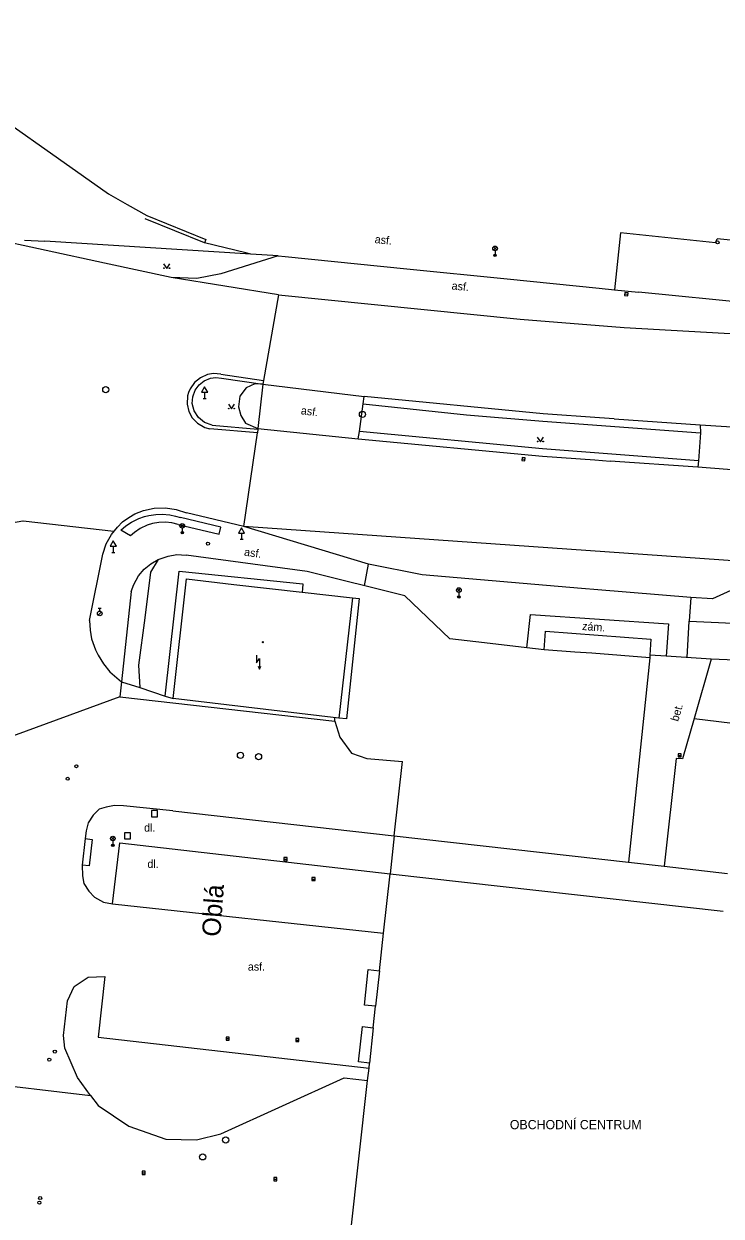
# Model space of a CAD drawing. Extents: x -602419 to -601554, y -1162937 to -1162362.
# Drawn here: x -601963.7 to -601907, y -1162488.6 to -1162391.7 of the extents above; entities that cross this region are included whole.
import ezdxf

# ---------------------------------------------------------------- set-up
doc = ezdxf.new("R2010")
doc.units = 0
doc.layers.add('Podklad', color=7, linetype='Continuous')

msp = doc.modelspace()

# ---------------------------------------------------------------- linework, layer by layer
at = {"layer": 'Podklad'}
for p, q in [((-601925.5225, -1162410.11), (-601925.2575, -1162409.845)), ((-601925.5225, -1162409.845), (-601925.2575, -1162410.11)), ((-601925.39, -1162410.165), (-601925.39, -1162410.54)), ((-601914.8544, -1162413.6782), (-601914.6056, -1162413.7018)), ((-601949.105, -1162422.1599), (-601948.855, -1162422.1599)), ((-601948.98, -1162421.6509), (-601948.98, -1162422.1599)), ((-601923.2142, -1162427.0756), (-601922.9658, -1162427.1044)), ((-601950.9325, -1162432.64), (-601950.6675, -1162432.375)), ((-601950.9325, -1162432.375), (-601950.6675, -1162432.64)), ((-601950.8, -1162432.695), (-601950.8, -1162433.07)), ((-601946.105, -1162433.6), (-601945.855, -1162433.6)), ((-601945.98, -1162433.091), (-601945.98, -1162433.6)), ((-601956.525, -1162434.68), (-601956.275, -1162434.68)), ((-601956.4, -1162434.171), (-601956.4, -1162434.68)), ((-601928.4625, -1162437.86), (-601928.1975, -1162437.595)), ((-601928.4625, -1162437.595), (-601928.1975, -1162437.86)), ((-601928.33, -1162437.915), (-601928.33, -1162438.29)), ((-601957.629, -1162439.756), (-601957.364, -1162439.491)), ((-601957.625, -1162439.1825), (-601957.375, -1162439.1825)), ((-601957.5, -1162439.4325), (-601957.5, -1162439.1825)), ((-601910.515, -1162451.15), (-601910.265, -1162451.15)), ((-601956.5725, -1162458.03), (-601956.3075, -1162457.765)), ((-601956.5725, -1162457.765), (-601956.3075, -1162458.03)), ((-601956.44, -1162458.085), (-601956.44, -1162458.46)), ((-601942.5349, -1162459.58), (-601942.2849, -1162459.58)), ((-601940.265, -1162461.2), (-601940.015, -1162461.2)), ((-601947.245, -1162474.15), (-601946.995, -1162474.15)), ((-601941.575, -1162474.27), (-601941.325, -1162474.27)), ((-601954.065, -1162485.05), (-601953.815, -1162485.05)), ((-601943.365, -1162485.57), (-601943.115, -1162485.57))]:
    msp.add_line(p, q, dxfattribs=at)
for points in [[(-601977.2199, -1162391.74), (-601975.27, -1162392.7), (-601971.17, -1162395.45), (-601969.4699, -1162396.62), (-601956.79, -1162405.54), (-601955.27, -1162406.4), (-601953.68, -1162407.3), (-601948.87, -1162409.25), (-601948.98, -1162409.52)], [(-601948.98, -1162409.52), (-601953.82, -1162407.57)], [(-601943, -1162410.58), (-601947.67, -1162412.04), (-601949.61, -1162412.43), (-601951.69, -1162412.34), (-601957.12, -1162411.17), (-601966.61, -1162409.13)], [(-601963.61, -1162409.31), (-601961.96, -1162409.4)], [(-601943, -1162410.58), (-601945.24, -1162410.44), (-601961.96, -1162409.4)], [(-601945.24, -1162410.44), (-601945.6297, -1162410.3452), (-601948.98, -1162409.52)], [(-601915.19, -1162408.71), (-601915.69, -1162413.329)], [(-601907.49, -1162409.52), (-601915.19, -1162408.71)], [(-601907.49, -1162409.52), (-601907.36, -1162409.19)], [(-601905.73, -1162409.35), (-601907.36, -1162409.19)], [(-601943, -1162410.58), (-601942.44, -1162410.63)], [(-601942.44, -1162410.63), (-601932.57, -1162411.63)], [(-601952.31, -1162411.235), (-601952.06, -1162411.61), (-601951.81, -1162411.235)], [(-601942.974, -1162413.752), (-601951.69, -1162412.34)], [(-601932.57, -1162411.63), (-601924.4099, -1162412.45)], [(-601924.4099, -1162412.45), (-601916.94, -1162413.2)], [(-601916.94, -1162413.2), (-601915.69, -1162413.33), (-601913.74, -1162413.53)], [(-601904.46, -1162414.45), (-601913.74, -1162413.53)], [(-601942.974, -1162413.752), (-601944.21, -1162420.7)], [(-601942.974, -1162413.752), (-601923.36, -1162415.7179), (-601914.899, -1162416.4019), (-601902.977, -1162417.0849), (-601901.6822, -1162417.0998), (-601901.1795, -1162417.1051), (-601901.1621, -1162417.1057), (-601897.689, -1162417.1448)], [(-601947.6599, -1162420.2), (-601948.27, -1162420.15), (-601948.76, -1162420.21), (-601949.32, -1162420.48), (-601949.81, -1162420.87), (-601950.15, -1162421.39), (-601950.29, -1162421.69), (-601950.36, -1162421.95), (-601950.4099, -1162422.64), (-601950.27, -1162423.2199), (-601949.98, -1162423.74), (-601949.55, -1162424.1599), (-601948.9699, -1162424.52), (-601948.56, -1162424.62)], [(-601947.6599, -1162420.2), (-601944.21, -1162420.7), (-601944.25, -1162420.99)], [(-601948.38, -1162424.33), (-601948.98, -1162424.11), (-601949.48, -1162423.7199), (-601949.83, -1162423.18), (-601949.98, -1162422.56), (-601949.94, -1162422.02), (-601949.76, -1162421.5), (-601949.43, -1162421.07), (-601949.02, -1162420.7199), (-601948.51, -1162420.51), (-601948.07, -1162420.46), (-601947.6, -1162420.51)], [(-601947.6, -1162420.51), (-601944.25, -1162420.99)], [(-601944.25, -1162420.99), (-601944.893, -1162420.9659), (-601945.606, -1162421.3069), (-601946.134, -1162421.988), (-601946.233, -1162422.8559), (-601946.046, -1162423.5369), (-601945.672, -1162424.1629), (-601944.65, -1162424.59)], [(-601944.25, -1162420.99), (-601944.65, -1162424.59)], [(-601944.25, -1162420.99), (-601936.01, -1162422.01)], [(-601936.1, -1162422.6), (-601936.01, -1162422.01)], [(-601916.92, -1162423.73), (-601921.49, -1162423.4), (-601936.01, -1162422.01)], [(-601947.05, -1162422.635), (-601946.8, -1162423.01), (-601946.55, -1162422.635)], [(-601936.1, -1162422.6), (-601927.7, -1162423.49), (-601921.5, -1162424), (-601908.71, -1162424.95), (-601908.87, -1162427.24), (-601921.54, -1162426.25), (-601936.4099, -1162424.86)], [(-601936.4099, -1162424.86), (-601936.1, -1162422.6)], [(-601915.7199, -1162423.81), (-601916.92, -1162423.73)], [(-601915.7199, -1162423.81), (-601908.74, -1162424.31), (-601906.58, -1162424.44), (-601903.8, -1162424.49), (-601902.51, -1162424.51)], [(-601944.6599, -1162424.65), (-601944.69, -1162424.95), (-601948.56, -1162424.62)], [(-601948.38, -1162424.33), (-601944.6599, -1162424.65)], [(-601901.6, -1162435.65), (-601903.1262, -1162435.5438), (-601903.2493, -1162435.535), (-601903.7384, -1162435.5009), (-601945.81, -1162432.57), (-601944.69, -1162424.95)], [(-601944.65, -1162424.59), (-601944.6599, -1162424.65)], [(-601944.65, -1162424.59), (-601936.5, -1162425.45)], [(-601936.5, -1162425.45), (-601936.4099, -1162424.86)], [(-601908.74, -1162424.31), (-601908.71, -1162424.95)], [(-601936.5, -1162425.45), (-601921.55, -1162426.86), (-601917.28, -1162427.1599)], [(-601921.96, -1162425.305), (-601921.71, -1162425.68), (-601921.46, -1162425.305)], [(-601917.28, -1162427.1599), (-601916.05, -1162427.25)], [(-601902.9099, -1162428.07), (-601904.04, -1162428.07), (-601906.5, -1162427.92), (-601908.93, -1162427.75), (-601916.05, -1162427.25)], [(-601908.87, -1162427.24), (-601908.93, -1162427.7495)], [(-601957.24, -1162434.82), (-601956.9699, -1162433.98), (-601956.55, -1162433.2), (-601956.07, -1162432.62), (-601955.64, -1162432.18), (-601955.13, -1162431.82), (-601954.64, -1162431.54), (-601953.94, -1162431.25), (-601953.07, -1162431.06), (-601952.17, -1162431.05), (-601951.28, -1162431.17), (-601950.45, -1162431.46)], [(-601955.8, -1162432.86), (-601955.37, -1162432.5), (-601954.9099, -1162432.2), (-601954.33, -1162431.9099), (-601953.86, -1162431.75), (-601953.52, -1162431.67), (-601952.94, -1162431.58), (-601952.42, -1162431.56), (-601951.82, -1162431.61), (-601951.35, -1162431.71), (-601950.95, -1162431.83)], [(-601951.14, -1162432.39), (-601947.8, -1162433.18), (-601947.6599, -1162432.61), (-601950.95, -1162431.83)], [(-601945.81, -1162432.57), (-601950.45, -1162431.46)], [(-601956.3597, -1162432.9701), (-601963.7232, -1162432.1419), (-601963.74, -1162432.1399), (-601965.62, -1162432.45)], [(-601955.01, -1162433.32), (-601955.8, -1162432.86)], [(-601951.14, -1162432.39), (-601951.65, -1162432.26), (-601952.17, -1162432.21), (-601952.69, -1162432.24), (-601953.21, -1162432.33), (-601953.65, -1162432.46), (-601954.2199, -1162432.73), (-601954.69, -1162433.04), (-601955.01, -1162433.32)], [(-601931.3, -1162436.5), (-601935.67, -1162435.63), (-601945.81, -1162432.57)], [(-601958.33, -1162440.2), (-601957.24, -1162434.82)], [(-601954.94, -1162437.83), (-601954.74, -1162437.27), (-601954.34, -1162436.57), (-601953.88, -1162436.03), (-601953.34, -1162435.59), (-601952.75, -1162435.23), (-601951.94, -1162434.96), (-601951.23, -1162434.84), (-601950.4699, -1162434.88)], [(-601952.75, -1162435.23), (-601953.37, -1162436.28), (-601953.83, -1162439.99), (-601954.36, -1162443.82), (-601954.25, -1162445.65)], [(-601922.82, -1162442.4099), (-601926.26, -1162442), (-601929.06, -1162441.69), (-601932.7199, -1162438.2), (-601940.64, -1162436.21), (-601950.4699, -1162434.88)], [(-601935.999, -1162437.3761), (-601935.67, -1162435.63)], [(-601952.18, -1162446.33), (-601951.04, -1162436.18), (-601941, -1162437.21), (-601941.04, -1162437.62), (-601941.07, -1162437.89)], [(-601918.37, -1162437.59), (-601931.3, -1162436.5)], [(-601903.87, -1162436.68), (-601907.73, -1162438.44)], [(-601951.54, -1162446.54), (-601950.46, -1162436.82)], [(-601950.46, -1162436.82), (-601946.61, -1162437.26)], [(-601946.61, -1162437.26), (-601941.07, -1162437.89)], [(-601917.05, -1162437.7), (-601918.37, -1162437.59)], [(-601909.5, -1162438.34), (-601917.05, -1162437.7)], [(-601954.94, -1162437.83), (-601955.7199, -1162445.17)], [(-601941.07, -1162437.89), (-601936.9699, -1162438.35)], [(-601936.9699, -1162438.35), (-601938.07, -1162448.12)], [(-601936.9699, -1162438.35), (-601936.42, -1162438.4099), (-601937.4699, -1162448.19), (-601938.07, -1162448.12)], [(-601909.5, -1162438.34), (-601909.62, -1162440.26)], [(-601907.73, -1162438.44), (-601909.5, -1162438.34)], [(-601958.33, -1162440.2), (-601958.29, -1162440.9699), (-601958.1599, -1162441.69), (-601957.84, -1162442.59), (-601957.63, -1162443), (-601957.2, -1162443.7199), (-601956.68, -1162444.37), (-601955.7199, -1162445.17)], [(-601922.82, -1162442.4099), (-601922.5, -1162439.71)], [(-601922.5, -1162439.71), (-601911.3, -1162440.4699)], [(-601911.3, -1162440.4699), (-601911.5, -1162443.1)], [(-601909.7886, -1162443.2075), (-601909.62, -1162440.26)], [(-601909.62, -1162440.26), (-601904.3, -1162440.49)], [(-601921.39, -1162442.58), (-601921.3, -1162441.06)], [(-601921.3, -1162441.06), (-601912.73, -1162441.7)], [(-601921.39, -1162442.58), (-601922.82, -1162442.4099)], [(-601918.9099, -1162442.77), (-601921.39, -1162442.58)], [(-601912.73, -1162441.7), (-601912.81, -1162443.01)], [(-601944.78, -1162443.02), (-601944.78, -1162443.645), (-601944.53, -1162443.27), (-601944.53, -1162444.145)], [(-601917.54, -1162442.86), (-601918.9099, -1162442.77)], [(-601912.82, -1162443.2199), (-601917.54, -1162442.86)], [(-601912.82, -1162443.2199), (-601914.55, -1162459.83)], [(-601912.81, -1162443.01), (-601912.82, -1162443.2199)], [(-601911.5, -1162443.1), (-601912.81, -1162443.01)], [(-601907.84, -1162443.33), (-601911.5, -1162443.1)], [(-601907.84, -1162443.33), (-601909.23, -1162448.1599)], [(-601904.63, -1162443.48), (-601907.84, -1162443.33)], [(-601944.6395, -1162443.9005), (-601944.53, -1162444.145), (-601944.4205, -1162443.9005)], [(-601955.7199, -1162445.17), (-601955.86, -1162446.4), (-601938.4, -1162448.38)], [(-601955.72, -1162445.17), (-601954.25, -1162445.65), (-601952.18, -1162446.33)], [(-601955.86, -1162446.4), (-601965.11, -1162449.78)], [(-601952.18, -1162446.33), (-601951.54, -1162446.54)], [(-601938.07, -1162448.12), (-601951.54, -1162446.54)], [(-601938.4, -1162448.38), (-601938.4081, -1162448.0803)], [(-601938.4, -1162448.38), (-601937.99, -1162449.68), (-601937.04, -1162450.9699), (-601935.81, -1162451.39), (-601932.92, -1162451.6599)], [(-601909.23, -1162448.1599), (-601910.17, -1162451.44)], [(-601909.23, -1162448.1599), (-601905.2, -1162448.65)], [(-601933.58, -1162457.68), (-601932.92, -1162451.6599)], [(-601910.68, -1162451.4099), (-601911.65, -1162460.15)], [(-601910.17, -1162451.44), (-601910.68, -1162451.4099)], [(-601951.57, -1162455.6599), (-601955.58, -1162455.24), (-601956.3, -1162455.2199), (-601956.99, -1162455.35), (-601957.55, -1162455.53), (-601958.03, -1162456.01), (-601958.45, -1162456.64), (-601958.59, -1162457.29), (-601958.68, -1162457.9099)], [(-601951.57, -1162455.6599), (-601933.58, -1162457.68)], [(-601958.68, -1162457.9099), (-601958.93, -1162460.06)], [(-601958.68, -1162457.9099), (-601958.11, -1162457.98), (-601958.37, -1162460.12), (-601958.93, -1162460.06)], [(-601933.58, -1162457.68), (-601933.92, -1162460.76)], [(-601933.58, -1162457.68), (-601914.55, -1162459.83)], [(-601956.46, -1162463.21), (-601955.88, -1162458.25), (-601933.92, -1162460.76)], [(-601914.55, -1162459.83), (-601911.65, -1162460.15)], [(-601958.93, -1162460.06), (-601958.9, -1162460.93), (-601958.79, -1162461.56), (-601958.38, -1162462.18), (-601957.93, -1162462.67), (-601957.2, -1162463.08), (-601956.46, -1162463.21)], [(-601934.44, -1162465.6), (-601933.92, -1162460.76)], [(-601933.92, -1162460.76), (-601906.86, -1162463.81)], [(-601911.65, -1162460.15), (-601906.52, -1162460.73)], [(-601956.46, -1162463.21), (-601934.44, -1162465.6)], [(-601934.77, -1162468.64), (-601934.44, -1162465.6)], [(-601935.99, -1162471.43), (-601935.69, -1162468.54)], [(-601935.69, -1162468.54), (-601934.77, -1162468.64)], [(-601934.77, -1162468.64), (-601935.09, -1162471.53)], [(-601958.25, -1162478.76), (-601959.32, -1162477.32), (-601960.33, -1162474.92), (-601960.44, -1162473.89), (-601960.11, -1162471.08), (-601959.58, -1162469.92), (-601958.44, -1162469.1599), (-601957.08, -1162469.1), (-601957.62, -1162474.04), (-601935.63, -1162476.54)], [(-601935.09, -1162471.53), (-601935.99, -1162471.43)], [(-601935.28, -1162473.28), (-601935.09, -1162471.53)], [(-601936.4699, -1162476.05), (-601936.1599, -1162473.18)], [(-601936.1599, -1162473.18), (-601935.28, -1162473.28)], [(-601935.28, -1162473.28), (-601935.59, -1162476.15)], [(-601935.59, -1162476.15), (-601936.4699, -1162476.05)], [(-601935.63, -1162476.54), (-601935.59, -1162476.15)], [(-601958.25, -1162478.76), (-601957.64, -1162479.59), (-601955.14, -1162481.27), (-601952.14, -1162482.32), (-601949.64, -1162482.36), (-601947.6599, -1162481.88), (-601937.6599, -1162477.34), (-601935.74, -1162477.55)], [(-601935.74, -1162477.55), (-601935.63, -1162476.54)], [(-601967.9, -1162477.63), (-601958.25, -1162478.76)], [(-601937.12, -1162490.04), (-601935.74, -1162477.55)]]:
    msp.add_lwpolyline(points, dxfattribs=at)
for points in [[(-601914.8662, -1162413.8027), (-601914.6173, -1162413.8262), (-601914.5938, -1162413.5773), (-601914.8427, -1162413.5538)], [(-601949.23, -1162421.6509), (-601948.73, -1162421.6509), (-601948.98, -1162421.2179)], [(-601923.2285, -1162427.1998), (-601922.9802, -1162427.2285), (-601922.9515, -1162426.9802), (-601923.1998, -1162426.9515)], [(-601946.23, -1162433.091), (-601945.73, -1162433.091), (-601945.98, -1162432.658)], [(-601956.65, -1162434.171), (-601956.15, -1162434.171), (-601956.4, -1162433.738)], [(-601910.515, -1162451.275), (-601910.265, -1162451.275), (-601910.265, -1162451.025), (-601910.515, -1162451.025)], [(-601953.3, -1162456.14), (-601952.8, -1162456.14), (-601952.8, -1162455.64), (-601953.3, -1162455.64)], [(-601955.49, -1162457.94), (-601954.99, -1162457.94), (-601954.99, -1162457.44), (-601955.49, -1162457.44)], [(-601942.5349, -1162459.705), (-601942.2849, -1162459.705), (-601942.2849, -1162459.455), (-601942.5349, -1162459.455)], [(-601940.265, -1162461.325), (-601940.015, -1162461.325), (-601940.015, -1162461.075), (-601940.265, -1162461.075)], [(-601947.245, -1162474.275), (-601946.995, -1162474.275), (-601946.995, -1162474.025), (-601947.245, -1162474.025)], [(-601941.575, -1162474.395), (-601941.325, -1162474.395), (-601941.325, -1162474.145), (-601941.575, -1162474.145)], [(-601954.065, -1162485.175), (-601953.815, -1162485.175), (-601953.815, -1162484.925), (-601954.065, -1162484.925)], [(-601943.365, -1162485.695), (-601943.115, -1162485.695), (-601943.115, -1162485.445), (-601943.365, -1162485.445)]]:
    msp.add_lwpolyline(points, close=True, dxfattribs=at)
for centre, radius in [((-601907.32, -1162409.49), 0.125), ((-601925.39, -1162409.9775), 0.1875), ((-601925.39, -1162410.54), 0.1), ((-601925.39, -1162410.54), 0.0723), ((-601925.39, -1162410.54), 0.0438), ((-601952.2851, -1162411.5849), 0.025), ((-601951.8354, -1162411.5849), 0.025), ((-601957.01, -1162421.45), 0.25), ((-601947.0251, -1162422.9849), 0.025), ((-601946.5754, -1162422.9849), 0.025), ((-601936.1599, -1162423.46), 0.25), ((-601921.9351, -1162425.6549), 0.025), ((-601921.4854, -1162425.6549), 0.025), ((-601950.8, -1162432.5075), 0.1875), ((-601950.8, -1162433.07), 0.1), ((-601950.8, -1162433.07), 0.0723), ((-601950.8, -1162433.07), 0.0438), ((-601948.71, -1162433.95), 0.125), ((-601928.33, -1162437.7275), 0.1875), ((-601928.33, -1162438.29), 0.1), ((-601928.33, -1162438.29), 0.0723), ((-601928.33, -1162438.29), 0.0438), ((-601957.5, -1162439.62), 0.1875), ((-601944.26, -1162441.96), 0.045), ((-601944.26, -1162441.96), 0.0199), ((-601946.07, -1162451.15), 0.25), ((-601944.6, -1162451.26), 0.25), ((-601959.4, -1162452.03), 0.125), ((-601960.1, -1162453.05), 0.125), ((-601956.44, -1162457.8975), 0.1875), ((-601956.44, -1162458.46), 0.1), ((-601956.44, -1162458.46), 0.0723), ((-601956.44, -1162458.46), 0.0438), ((-601961.15, -1162475.21), 0.125), ((-601961.6, -1162475.86), 0.125), ((-601947.27, -1162482.39), 0.25), ((-601949.14, -1162483.76), 0.25), ((-601962.34, -1162487.1), 0.125), ((-601962.4, -1162487.48), 0.125)]:
    msp.add_circle(centre, radius, dxfattribs=at)

# ---------------------------------------------------------------- texts
for s, height, rotation, p in [('asf.', 0.65, 354.13, (-601935.19, -1162409.54)), ('asf.', 0.65, 354.377589, (-601928.94, -1162413.31)), ('asf.', 0.65, 352.94, (-601941.19, -1162423.44)), ('asf.', 0.65, 352.29, (-601945.8, -1162434.93)), (' zám.', 0.65, 356.12, (-601918.58, -1162440.95)), ('bet.', 0.65, 73.97, (-601910.52, -1162448.44)), ('Oblá', 1.5, 85.95, (-601947.71, -1162465.9099))]:
    msp.add_text(s, height=height, rotation=rotation, dxfattribs=at).set_placement(p)
for s, height, p in [('dl.', 0.65, (-601953.9, -1162457.34)), ('dl.', 0.65, (-601953.63, -1162460.29)), ('asf.', 0.65, (-601945.4699, -1162468.63)), ('OBCHODNÍ CENTRUM', 0.75, (-601924.19, -1162481.51))]:
    msp.add_text(s, height=height, dxfattribs=at).set_placement(p)

doc.saveas('drawing.dxf')
